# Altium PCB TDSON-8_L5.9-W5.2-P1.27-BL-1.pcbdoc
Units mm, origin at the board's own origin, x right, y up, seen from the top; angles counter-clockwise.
Board outline 18.11 x 19.83 mm, 2 copper layers (Top Layer, Bottom Layer), stack 0 mm thick; 1 components, 0 nets, 5 pads, 0 vias.
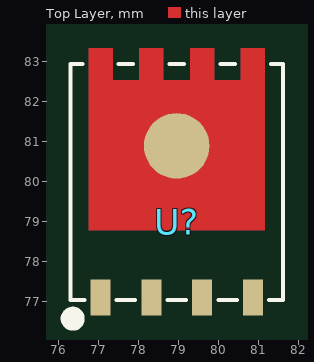
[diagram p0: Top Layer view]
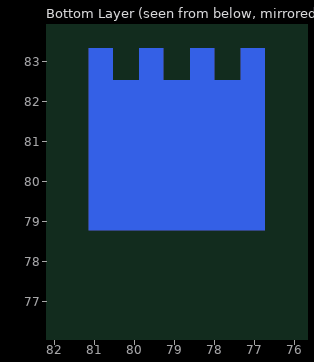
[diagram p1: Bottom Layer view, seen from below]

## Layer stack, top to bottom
Top Layer: signal copper (thickness not stored)
Bottom Layer: signal copper (thickness not stored)

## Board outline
87.96,69.85 69.85,69.85 69.85,89.675 87.96,89.675

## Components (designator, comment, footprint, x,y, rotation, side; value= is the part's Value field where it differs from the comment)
U? "" TDSON-8_L5.9-W5.2-P1.27-BL-1 78.95,78.875 r0 top

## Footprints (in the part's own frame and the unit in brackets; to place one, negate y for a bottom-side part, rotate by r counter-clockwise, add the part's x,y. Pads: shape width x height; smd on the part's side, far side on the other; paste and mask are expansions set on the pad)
TDSON-8_L5.9-W5.2-P1.27-BL-1 [mm]
  rect 0.5x0.9 smd paste-100 mask+0.05: 1(-1.905,-1.775) 2(-0.635,-1.775) 3(0.635,-1.775) 4(1.905,-1.775)
  round 1.638 smd: 5(0,2.012)
  Top Layer region: -2.205,-0.1 2.205,-0.1 2.205,4.45 1.605,4.45 1.605,3.65 0.935,3.65 0.935,4.45 0.335,4.45 0.335,3.65 -0.335,3.65 -0.335,4.45 -0.935,4.45 -0.935,3.65 -1.605,3.65 -1.605,4.45 -2.205,4.45
  Bottom Layer region: -2.205,-0.1 2.205,-0.1 2.205,4.45 1.605,4.45 1.605,3.65 0.935,3.65 0.935,4.45 0.335,4.45 0.335,3.65 -0.335,3.65 -0.335,4.45 -0.935,4.45 -0.935,3.65 -1.605,3.65 -1.605,4.45 -2.205,4.45
  Multi-Layer region: -2.205,-0.1 2.205,-0.1 2.205,4.45 1.605,4.45 1.605,3.65 0.935,3.65 0.935,4.45 0.335,4.45 0.335,3.65 -0.335,3.65 -0.335,4.45 -0.935,4.45 -0.935,3.65 -1.605,3.65 -1.605,4.45 -2.205,4.45
  silkscreen extent -2.75,-2.46 2.66,4.06

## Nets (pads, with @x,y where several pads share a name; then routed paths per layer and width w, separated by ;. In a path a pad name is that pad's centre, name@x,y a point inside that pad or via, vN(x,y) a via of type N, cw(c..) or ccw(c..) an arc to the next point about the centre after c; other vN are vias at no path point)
pads on no net: U?.1 U?.2 U?.3 U?.4 U?.5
